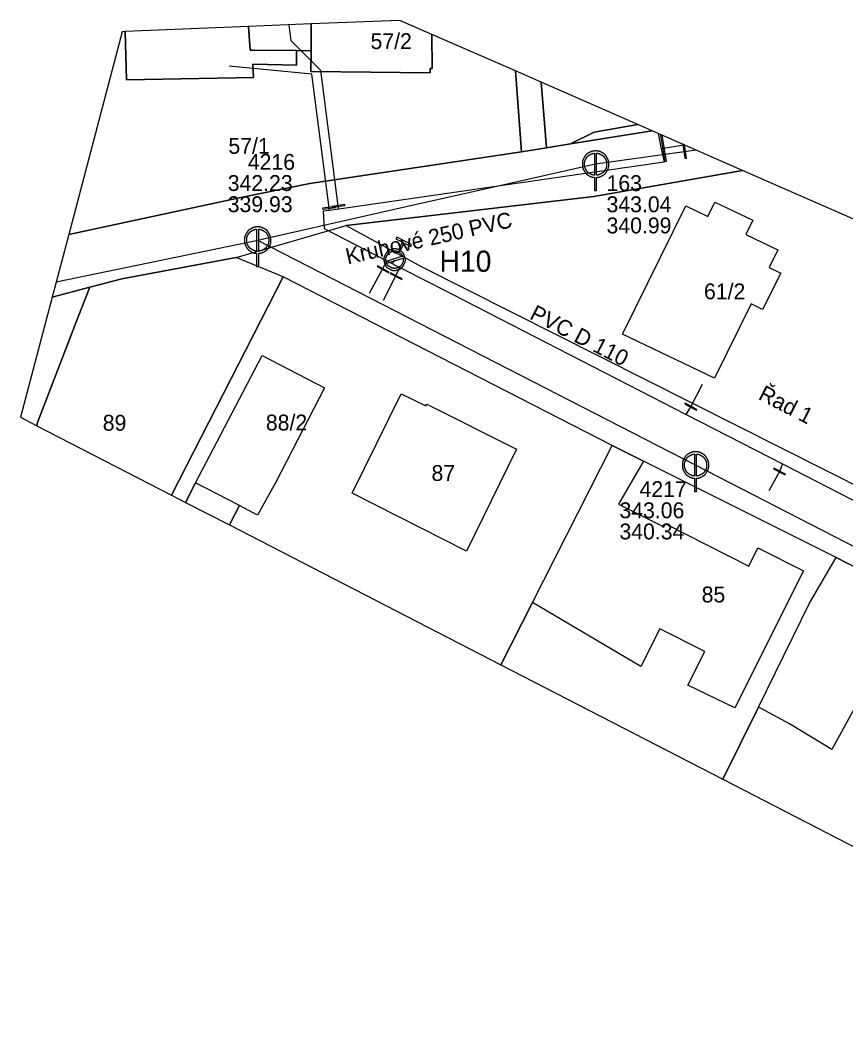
# Model space of a CAD drawing. Extents: x -559654 to -559448, y -1076607 to -1076478.
# Drawn here: x -559654.1 to -559576.1, y -1076574.1 to -1076478 of the extents above; entities that cross this region are included whole.
import ezdxf

# ---------------------------------------------------------------- set-up
doc = ezdxf.new("R2010")
doc.units = 0
for name, color, linetype in [('Armatura vodovodní', 7, 'Continuous'), ('Default', 7, 'Continuous'), ('Hydrant', 7, 'Continuous'), ('Kanalizační stoka', 7, 'Continuous'), ('Kanalizační šachta', 7, 'Continuous'), ('Označení hydrantu', 7, 'Continuous'), ('Parcela-polygon', 7, 'Continuous'), ('Parcela-text', 7, 'Continuous'), ('Popis kmenové stoky', 7, 'Continuous'), ('Popis šachty', 7, 'Continuous'), ('Vodovodní přípojka', 7, 'Continuous'), ('Vodovodní řad', 7, 'Continuous'), ('Řad vodovodní označení', 7, 'Continuous'), ('Řad vodovodní popis', 7, 'Continuous')]:
    doc.layers.add(name, color=color, linetype=linetype)

msp = doc.modelspace()

# ---------------------------------------------------------------- linework, layer by layer
at = {"layer": 'Armatura vodovodní'}
for p, q in [((-559593.444, -1076488.847), (-559593.464, -1076488.838)), ((-559591.347, -1076489.765), (-559591.516, -1076489.691))]:
    msp.add_line(p, q, dxfattribs=at)
for points in [[(-559593.464, -1076488.838), (-559593.6, -1076488.859), (-559593.209, -1076491.329), (-559593.055, -1076491.304), (-559593.444, -1076488.847)], [(-559591.516, -1076489.691), (-559591.306, -1076491.024), (-559591.152, -1076490.999), (-559591.347, -1076489.765)]]:
    msp.add_lwpolyline(points, dxfattribs=at)
for points in [[(-559624.684, -1076495.642), (-559623.444, -1076495.482), (-559623.454, -1076495.405), (-559624.694, -1076495.564)], [(-559625.547, -1076495.824), (-559624.307, -1076495.665), (-559624.317, -1076495.587), (-559625.557, -1076495.747)], [(-559619.308, -1076501.848), (-559619.271, -1076501.779), (-559620.371, -1076501.186), (-559620.408, -1076501.255)], [(-559618.067, -1076502.479), (-559618.032, -1076502.41), (-559619.143, -1076501.839), (-559619.179, -1076501.908)], [(-559590.198, -1076514.822), (-559590.163, -1076514.753), (-559591.274, -1076514.182), (-559591.31, -1076514.251)], [(-559581.82, -1076520.94), (-559581.785, -1076520.871), (-559582.901, -1076520.307), (-559582.936, -1076520.377)]]:
    msp.add_lwpolyline(points, close=True, dxfattribs=at)
at = {"layer": 'Default'}
for points in [[(-559600.365, -1076490.491), (-559600.564, -1076490.599), (-559600.719, -1076490.752), (-559600.832, -1076490.953)], [(-559599.75, -1076490.33), (-559599.962, -1076490.33), (-559600.167, -1076490.384), (-559600.365, -1076490.491)], [(-559600.265, -1076490.674), (-559600.122, -1076490.598), (-559599.984, -1076490.554), (-559599.853, -1076490.542)], [(-559599.136, -1076490.491), (-559599.335, -1076490.384), (-559599.54, -1076490.33), (-559599.75, -1076490.33)], [(-559599.647, -1076490.542), (-559599.516, -1076490.554), (-559599.379, -1076490.598), (-559599.237, -1076490.674)], [(-559598.668, -1076490.953), (-559598.781, -1076490.752), (-559598.937, -1076490.599), (-559599.136, -1076490.491)], [(-559600.832, -1076490.953), (-559600.944, -1076491.153), (-559601, -1076491.362), (-559601, -1076491.58)], [(-559601, -1076491.58), (-559601, -1076491.796), (-559600.945, -1076492.004), (-559600.835, -1076492.203)], [(-559600.792, -1076491.58), (-559600.792, -1076491.399), (-559600.746, -1076491.226), (-559600.653, -1076491.059)], [(-559600.656, -1076492.098), (-559600.747, -1076491.933), (-559600.792, -1076491.761), (-559600.792, -1076491.58)], [(-559600.653, -1076491.059), (-559600.561, -1076490.892), (-559600.431, -1076490.764), (-559600.265, -1076490.674)], [(-559599.237, -1076490.674), (-559599.071, -1076490.764), (-559598.941, -1076490.892), (-559598.848, -1076491.059)], [(-559598.848, -1076491.059), (-559598.754, -1076491.226), (-559598.708, -1076491.399), (-559598.708, -1076491.58)], [(-559598.708, -1076491.58), (-559598.708, -1076491.761), (-559598.753, -1076491.933), (-559598.844, -1076492.098)], [(-559598.5, -1076491.58), (-559598.5, -1076491.362), (-559598.556, -1076491.153), (-559598.668, -1076490.953)], [(-559598.665, -1076492.203), (-559598.555, -1076492.004), (-559598.5, -1076491.796), (-559598.5, -1076491.58)], [(-559600.835, -1076492.203), (-559600.725, -1076492.401), (-559600.571, -1076492.555), (-559600.373, -1076492.664)], [(-559600.27, -1076492.481), (-559600.436, -1076492.39), (-559600.565, -1076492.262), (-559600.656, -1076492.098)], [(-559599.853, -1076492.615), (-559599.989, -1076492.605), (-559600.128, -1076492.561), (-559600.27, -1076492.481)], [(-559599.228, -1076492.481), (-559599.371, -1076492.561), (-559599.511, -1076492.605), (-559599.647, -1076492.615)], [(-559598.844, -1076492.098), (-559598.935, -1076492.262), (-559599.063, -1076492.39), (-559599.228, -1076492.481)], [(-559599.127, -1076492.664), (-559598.929, -1076492.555), (-559598.775, -1076492.401), (-559598.665, -1076492.203)], [(-559600.373, -1076492.664), (-559600.198, -1076492.762), (-559600.025, -1076492.816), (-559599.853, -1076492.828)], [(-559599.647, -1076492.828), (-559599.475, -1076492.816), (-559599.302, -1076492.762), (-559599.127, -1076492.664)], [(-559632.772, -1076498.132), (-559632.884, -1076498.332), (-559632.94, -1076498.542), (-559632.94, -1076498.76)], [(-559632.306, -1076497.671), (-559632.504, -1076497.778), (-559632.66, -1076497.932), (-559632.772, -1076498.132)], [(-559632.733, -1076498.76), (-559632.733, -1076498.579), (-559632.686, -1076498.405), (-559632.594, -1076498.238)], [(-559632.594, -1076498.238), (-559632.501, -1076498.072), (-559632.371, -1076497.943), (-559632.205, -1076497.854)], [(-559631.69, -1076497.51), (-559631.902, -1076497.51), (-559632.107, -1076497.563), (-559632.306, -1076497.671)], [(-559632.205, -1076497.854), (-559632.062, -1076497.777), (-559631.925, -1076497.734), (-559631.793, -1076497.722)], [(-559631.076, -1076497.671), (-559631.276, -1076497.563), (-559631.48, -1076497.51), (-559631.69, -1076497.51)], [(-559631.588, -1076497.722), (-559631.456, -1076497.734), (-559631.319, -1076497.777), (-559631.178, -1076497.854)], [(-559631.178, -1076497.854), (-559631.012, -1076497.943), (-559630.882, -1076498.072), (-559630.788, -1076498.238)], [(-559630.609, -1076498.132), (-559630.721, -1076497.932), (-559630.877, -1076497.778), (-559631.076, -1076497.671)], [(-559630.788, -1076498.238), (-559630.695, -1076498.405), (-559630.648, -1076498.579), (-559630.648, -1076498.76)], [(-559630.44, -1076498.76), (-559630.44, -1076498.542), (-559630.496, -1076498.332), (-559630.609, -1076498.132)], [(-559632.94, -1076498.76), (-559632.94, -1076498.976), (-559632.885, -1076499.184), (-559632.776, -1076499.382)], [(-559632.596, -1076499.277), (-559632.687, -1076499.113), (-559632.733, -1076498.94), (-559632.733, -1076498.76)], [(-559632.21, -1076499.661), (-559632.376, -1076499.569), (-559632.505, -1076499.442), (-559632.596, -1076499.277)], [(-559630.785, -1076499.277), (-559630.876, -1076499.442), (-559631.003, -1076499.569), (-559631.168, -1076499.661)], [(-559630.648, -1076498.76), (-559630.648, -1076498.94), (-559630.693, -1076499.113), (-559630.785, -1076499.277)], [(-559630.605, -1076499.382), (-559630.495, -1076499.184), (-559630.44, -1076498.976), (-559630.44, -1076498.76)], [(-559632.776, -1076499.382), (-559632.666, -1076499.581), (-559632.511, -1076499.735), (-559632.313, -1076499.844)], [(-559632.313, -1076499.844), (-559632.139, -1076499.941), (-559631.965, -1076499.996), (-559631.793, -1076500.007)], [(-559631.793, -1076499.795), (-559631.93, -1076499.785), (-559632.069, -1076499.74), (-559632.21, -1076499.661)], [(-559631.168, -1076499.661), (-559631.311, -1076499.74), (-559631.451, -1076499.785), (-559631.588, -1076499.795)], [(-559631.588, -1076500.007), (-559631.415, -1076499.996), (-559631.242, -1076499.941), (-559631.068, -1076499.844)], [(-559631.068, -1076499.844), (-559630.869, -1076499.735), (-559630.715, -1076499.581), (-559630.605, -1076499.382)], [(-559619.642, -1076500.149), (-559619.768, -1076500.395), (-559619.789, -1076500.649), (-559619.704, -1076500.911)], [(-559619.059, -1076499.652), (-559619.321, -1076499.737), (-559619.515, -1076499.903), (-559619.642, -1076500.149)], [(-559619.551, -1076500.763), (-559619.589, -1076500.581), (-559619.564, -1076500.403), (-559619.475, -1076500.231)], [(-559619.475, -1076500.231), (-559619.372, -1076500.03), (-559619.214, -1076499.896), (-559619.001, -1076499.828)], [(-559618.38, -1076499.676), (-559618.6, -1076499.583), (-559618.827, -1076499.575), (-559619.059, -1076499.652)], [(-559619.001, -1076499.828), (-559618.788, -1076499.759), (-559618.582, -1076499.777), (-559618.381, -1076499.879)], [(-559618.381, -1076499.879), (-559618.209, -1076499.968), (-559618.085, -1076500.098), (-559618.01, -1076500.268)], [(-559617.798, -1076500.3), (-559617.872, -1076500.067), (-559618.01, -1076499.888), (-559618.213, -1076499.762)], [(-559619.704, -1076500.911), (-559619.62, -1076501.174), (-559619.455, -1076501.368), (-559619.211, -1076501.493)], [(-559619.124, -1076501.325), (-559619.296, -1076501.237), (-559619.419, -1076501.109), (-559619.494, -1076500.942)], [(-559618.03, -1076500.974), (-559618.133, -1076501.174), (-559618.291, -1076501.308), (-559618.505, -1076501.376)], [(-559618.447, -1076501.558), (-559618.184, -1076501.474), (-559617.99, -1076501.309), (-559617.863, -1076501.064)], [(-559617.953, -1076500.447), (-559617.916, -1076500.627), (-559617.942, -1076500.802), (-559618.03, -1076500.974)], [(-559617.863, -1076501.064), (-559617.737, -1076500.817), (-559617.715, -1076500.562), (-559617.798, -1076500.3)], [(-559619.211, -1076501.493), (-559618.964, -1076501.62), (-559618.709, -1076501.642), (-559618.447, -1076501.558)], [(-559618.505, -1076501.376), (-559618.719, -1076501.444), (-559618.925, -1076501.427), (-559619.124, -1076501.325)], [(-559591.38, -1076519.39), (-559591.492, -1076519.59), (-559591.548, -1076519.799), (-559591.548, -1076520.017)], [(-559590.913, -1076518.928), (-559591.112, -1076519.036), (-559591.267, -1076519.189), (-559591.38, -1076519.39)], [(-559591.34, -1076520.017), (-559591.34, -1076519.836), (-559591.294, -1076519.663), (-559591.201, -1076519.496)], [(-559591.201, -1076519.496), (-559591.109, -1076519.329), (-559590.979, -1076519.201), (-559590.813, -1076519.111)], [(-559590.298, -1076518.767), (-559590.51, -1076518.767), (-559590.715, -1076518.821), (-559590.913, -1076518.928)], [(-559590.813, -1076519.111), (-559590.67, -1076519.035), (-559590.532, -1076518.991), (-559590.401, -1076518.979)], [(-559589.684, -1076518.928), (-559589.883, -1076518.821), (-559590.088, -1076518.767), (-559590.298, -1076518.767)], [(-559590.195, -1076518.979), (-559590.064, -1076518.991), (-559589.927, -1076519.035), (-559589.785, -1076519.111)], [(-559589.785, -1076519.111), (-559589.619, -1076519.201), (-559589.489, -1076519.329), (-559589.396, -1076519.496)], [(-559589.216, -1076519.39), (-559589.329, -1076519.189), (-559589.485, -1076519.036), (-559589.684, -1076518.928)], [(-559589.396, -1076519.496), (-559589.302, -1076519.663), (-559589.256, -1076519.836), (-559589.256, -1076520.017)], [(-559589.048, -1076520.017), (-559589.048, -1076519.799), (-559589.104, -1076519.59), (-559589.216, -1076519.39)], [(-559591.548, -1076520.017), (-559591.548, -1076520.233), (-559591.493, -1076520.441), (-559591.383, -1076520.64)], [(-559591.204, -1076520.535), (-559591.295, -1076520.37), (-559591.34, -1076520.198), (-559591.34, -1076520.017)], [(-559589.256, -1076520.017), (-559589.256, -1076520.198), (-559589.301, -1076520.37), (-559589.392, -1076520.535)], [(-559589.213, -1076520.64), (-559589.103, -1076520.441), (-559589.048, -1076520.233), (-559589.048, -1076520.017)], [(-559591.383, -1076520.64), (-559591.273, -1076520.838), (-559591.119, -1076520.992), (-559590.921, -1076521.101)], [(-559590.818, -1076520.918), (-559590.984, -1076520.827), (-559591.113, -1076520.699), (-559591.204, -1076520.535)], [(-559590.921, -1076521.101), (-559590.746, -1076521.199), (-559590.573, -1076521.253), (-559590.401, -1076521.265)], [(-559590.401, -1076521.052), (-559590.537, -1076521.042), (-559590.676, -1076520.998), (-559590.818, -1076520.918)], [(-559589.776, -1076520.918), (-559589.919, -1076520.998), (-559590.059, -1076521.042), (-559590.195, -1076521.052)], [(-559590.195, -1076521.265), (-559590.023, -1076521.253), (-559589.85, -1076521.199), (-559589.675, -1076521.101)], [(-559589.392, -1076520.535), (-559589.483, -1076520.699), (-559589.611, -1076520.827), (-559589.776, -1076520.918)], [(-559589.675, -1076521.101), (-559589.477, -1076520.992), (-559589.323, -1076520.838), (-559589.213, -1076520.64)]]:
    msp.add_open_spline(points, degree=2, dxfattribs=at)
at = {"layer": 'Hydrant'}
for points in [[(-559618.213, -1076499.762), (-559617.84, -1076499.036), (-559617.229, -1076499.35), (-559617.143, -1076499.183), (-559618.533, -1076498.469), (-559618.618, -1076498.636), (-559618.007, -1076498.95), (-559618.38, -1076499.676)], [(-559618.01, -1076500.268), (-559619.551, -1076500.763)], [(-559619.494, -1076500.942), (-559617.953, -1076500.447)]]:
    msp.add_lwpolyline(points, dxfattribs=at)
at = {"layer": 'Kanalizační stoka'}
for points in [[(-559590.249, -1076490.246), (-559599.751, -1076491.578)], [(-559599.751, -1076491.578), (-559611.6, -1076494.252), (-559617.94, -1076495.683), (-559631.679, -1076498.783)], [(-559631.679, -1076498.783), (-559650.75, -1076502.72)], [(-559590.298, -1076520.017), (-559631.679, -1076498.783)], [(-559542.148, -1076544.787), (-559590.298, -1076520.017)]]:
    msp.add_lwpolyline(points, dxfattribs=at)
at = {"layer": 'Kanalizační šachta'}
for points in [[(-559599.853, -1076490.542), (-559599.853, -1076492.615)], [(-559599.647, -1076492.615), (-559599.647, -1076490.542)], [(-559599.853, -1076494.08), (-559599.647, -1076494.08), (-559599.647, -1076492.828)], [(-559599.853, -1076492.828), (-559599.853, -1076494.08)], [(-559631.793, -1076497.722), (-559631.793, -1076499.795)], [(-559631.588, -1076499.795), (-559631.588, -1076497.722)], [(-559631.793, -1076501.26), (-559631.588, -1076501.26), (-559631.588, -1076500.007)], [(-559631.793, -1076500.007), (-559631.793, -1076501.26)], [(-559590.401, -1076518.979), (-559590.401, -1076521.052)], [(-559590.195, -1076521.052), (-559590.195, -1076518.979)], [(-559590.401, -1076522.517), (-559590.195, -1076522.517), (-559590.195, -1076521.265)], [(-559590.401, -1076521.265), (-559590.401, -1076522.517)]]:
    msp.add_lwpolyline(points, dxfattribs=at)
at = {"layer": 'Parcela-polygon'}
for p, q in [((-559632.55, -1076478.567), (-559644.223, -1076479.044)), ((-559626.629, -1076478.326), (-559632.55, -1076478.567)), ((-559607.331, -1076482.764), (-559615.215, -1076479.31)), ((-559604.902, -1076483.828), (-559607.331, -1076482.764)), ((-559595.756, -1076487.834), (-559604.902, -1076483.828)), ((-559594.403, -1076488.426), (-559595.756, -1076487.834)), ((-559585.87, -1076492.164), (-559594.403, -1076488.426)), ((-559562.902, -1076502.225), (-559585.87, -1076492.164)), ((-559649.556, -1076498.21), (-559651.127, -1076504.146)), ((-559652.566, -1076516.299), (-559639.844, -1076522.856)), ((-559639.844, -1076522.856), (-559638.51, -1076523.543)), ((-559638.51, -1076523.543), (-559634.361, -1076525.682)), ((-559634.361, -1076525.682), (-559608.706, -1076538.904)), ((-559608.706, -1076538.904), (-559587.727, -1076549.716)), ((-559587.727, -1076549.716), (-559569.856, -1076558.926))]:
    msp.add_line(p, q, dxfattribs=at)
for points in [[(-559615.215, -1076479.31), (-559618.245, -1076477.983), (-559626.629, -1076478.326)], [(-559644.223, -1076479.044), (-559644.488, -1076479.055), (-559649.556, -1076498.21)], [(-559644.223, -1076479.044), (-559644.1, -1076483.61), (-559632.1, -1076483.37), (-559632.14, -1076482.13), (-559628.02, -1076482.21), (-559628.03, -1076480.84), (-559632.19, -1076480.79), (-559632.39, -1076480.79), (-559632.55, -1076478.567)], [(-559615.215, -1076479.31), (-559615.2, -1076482.53), (-559615.4, -1076482.53), (-559615.4, -1076482.93), (-559626.68, -1076482.81), (-559626.64, -1076480.85), (-559628.03, -1076480.84), (-559628.02, -1076482.21), (-559632.14, -1076482.13), (-559632.1, -1076483.37), (-559644.1, -1076483.61), (-559644.223, -1076479.044)], [(-559632.55, -1076478.567), (-559632.39, -1076480.79), (-559632.19, -1076480.79), (-559628.03, -1076480.84), (-559626.64, -1076480.85), (-559626.629, -1076478.326)], [(-559626.629, -1076478.326), (-559626.64, -1076480.85), (-559626.68, -1076482.81), (-559615.4, -1076482.93), (-559615.4, -1076482.53), (-559615.2, -1076482.53), (-559615.215, -1076479.31)], [(-559649.556, -1076498.21), (-559633.28, -1076494.72), (-559626.76, -1076493.41), (-559606.75, -1076490.41), (-559607.331, -1076482.764)], [(-559607.331, -1076482.764), (-559606.75, -1076490.41), (-559604.4, -1076490.03), (-559604.902, -1076483.828)], [(-559604.902, -1076483.828), (-559604.4, -1076490.03), (-559602.13, -1076489.67), (-559599.89, -1076488.55), (-559595.756, -1076487.834)], [(-559594.403, -1076488.426), (-559602.13, -1076489.67), (-559604.4, -1076490.03), (-559606.75, -1076490.41), (-559626.76, -1076493.41), (-559633.28, -1076494.72), (-559649.556, -1076498.21)], [(-559595.756, -1076487.834), (-559599.89, -1076488.55), (-559602.13, -1076489.67), (-559594.403, -1076488.426)], [(-559651.127, -1076504.146), (-559647.56, -1076503.2), (-559644.55, -1076502.4), (-559633.72, -1076500.39), (-559623.33, -1076497.36), (-559599.9, -1076494.63), (-559585.87, -1076492.164)], [(-559585.87, -1076492.164), (-559599.9, -1076494.63), (-559623.33, -1076497.36), (-559616.19, -1076501.28), (-559573.81, -1076522.62), (-559565.46, -1076506.3), (-559562.902, -1076502.225)], [(-559588.51, -1076511.82), (-559597.22, -1076507.66), (-559591.23, -1076495.51), (-559589.14, -1076496.51), (-559588.49, -1076495.16), (-559584.88, -1076496.88), (-559585.53, -1076498.23), (-559582.52, -1076499.67), (-559583.34, -1076501.33), (-559582.25, -1076501.87), (-559583.98, -1076505.31), (-559585.04, -1076504.78), (-559588.51, -1076511.82)], [(-559639.844, -1076522.856), (-559629.27, -1076502.23), (-559633.72, -1076500.39), (-559644.55, -1076502.4), (-559647.56, -1076503.2), (-559648.65, -1076506.01), (-559652.51, -1076515.99), (-559652.566, -1076516.299)], [(-559608.706, -1076538.904), (-559605.71, -1076533), (-559598.18, -1076518.16), (-559629.27, -1076502.23), (-559639.844, -1076522.856)], [(-559652.566, -1076516.299), (-559652.51, -1076515.99), (-559648.65, -1076506.01), (-559647.56, -1076503.2), (-559651.127, -1076504.146)], [(-559651.127, -1076504.146), (-559654.129, -1076515.494), (-559652.566, -1076516.299)], [(-559638.51, -1076523.543), (-559637.58, -1076521.71), (-559635.9, -1076518.51), (-559631.27, -1076509.65), (-559625.37, -1076512.71), (-559629.99, -1076521.64), (-559631.71, -1076524.76), (-559633.42, -1076523.85), (-559634.361, -1076525.682)], [(-559615.79, -1076514.42), (-559615.71, -1076514.27), (-559607.23, -1076518.52), (-559611.96, -1076528.15), (-559622.75, -1076522.67), (-559618.13, -1076513.29), (-559615.79, -1076514.42)], [(-559587.727, -1076549.716), (-559584.34, -1076542.9), (-559579.53, -1076533.07), (-559577, -1076528.76), (-559595.22, -1076519.64), (-559597.57, -1076523.72), (-559593.3, -1076525.87), (-559593.14, -1076525.56), (-559585.27, -1076529.56), (-559584.4, -1076527.85), (-559580.11, -1076530), (-559586.58, -1076542.95), (-559591.03, -1076540.81), (-559589.41, -1076537.64), (-559593.68, -1076535.49), (-559595.48, -1076539.07), (-559605.71, -1076533), (-559608.706, -1076538.904)], [(-559634.361, -1076525.682), (-559633.42, -1076523.85), (-559637.58, -1076521.71), (-559638.51, -1076523.543)], [(-559569.856, -1076558.926), (-559559.21, -1076537.91), (-559568.79, -1076532.99), (-559570.76, -1076536.75), (-559564.14, -1076540.06), (-559567.52, -1076546.81), (-559575.28, -1076543.01), (-559577.42, -1076546.89), (-559581.41, -1076544.47), (-559584.1, -1076543.03), (-559584.34, -1076542.9), (-559587.727, -1076549.716)]]:
    msp.add_lwpolyline(points, dxfattribs=at)
for points in [[(-559582.25, -1076501.87), (-559583.98, -1076505.31), (-559585.04, -1076504.78), (-559588.51, -1076511.82), (-559597.22, -1076507.66), (-559591.23, -1076495.51), (-559589.14, -1076496.51), (-559588.49, -1076495.16), (-559584.88, -1076496.88), (-559585.53, -1076498.23), (-559582.52, -1076499.67), (-559583.34, -1076501.33)], [(-559598.18, -1076518.16), (-559629.27, -1076502.23), (-559633.72, -1076500.39), (-559623.33, -1076497.36), (-559616.19, -1076501.28), (-559573.81, -1076522.62), (-559555.89, -1076531.62), (-559538.18, -1076540.8), (-559520.56, -1076549.81), (-559502.55, -1076559.13), (-559485.32, -1076568.19), (-559489.07, -1076574.14), (-559505.11, -1076565.7), (-559518.69, -1076558.79), (-559538.34, -1076548.73), (-559546.54, -1076544.48), (-559559.21, -1076537.91), (-559568.79, -1076532.99), (-559577, -1076528.76), (-559595.22, -1076519.64)], [(-559637.58, -1076521.71), (-559635.9, -1076518.51), (-559631.27, -1076509.65), (-559625.37, -1076512.71), (-559629.99, -1076521.64), (-559631.71, -1076524.76), (-559633.42, -1076523.85)], [(-559607.23, -1076518.52), (-559611.96, -1076528.15), (-559622.75, -1076522.67), (-559618.13, -1076513.29), (-559615.79, -1076514.42), (-559615.71, -1076514.27)], [(-559593.68, -1076535.49), (-559595.48, -1076539.07), (-559605.71, -1076533), (-559598.18, -1076518.16), (-559595.22, -1076519.64), (-559597.57, -1076523.72), (-559593.3, -1076525.87), (-559593.14, -1076525.56), (-559585.27, -1076529.56), (-559584.4, -1076527.85), (-559580.11, -1076530), (-559586.58, -1076542.95), (-559591.03, -1076540.81), (-559589.41, -1076537.64)], [(-559568.79, -1076532.99), (-559570.76, -1076536.75), (-559564.14, -1076540.06), (-559567.52, -1076546.81), (-559575.28, -1076543.01), (-559577.42, -1076546.89), (-559581.41, -1076544.47), (-559584.1, -1076543.03), (-559584.34, -1076542.9), (-559579.53, -1076533.07), (-559577, -1076528.76)]]:
    msp.add_lwpolyline(points, close=True, dxfattribs=at)
at = {"layer": 'Vodovodní přípojka'}
for points in [[(-559624.029, -1076495.839), (-559624.069, -1076495.524), (-559625.716, -1076482.727), (-559628.528, -1076479.914), (-559628.703, -1076478.41)], [(-559624.9, -1076495.951), (-559624.931, -1076495.709), (-559624.932, -1076495.707), (-559626.559, -1076483.055), (-559634.387, -1076482.305)], [(-559619.475, -1076500.701), (-559621.147, -1076503.805)], [(-559618.245, -1076501.333), (-559619.829, -1076504.47)], [(-559591.192, -1076515.237), (-559590.737, -1076514.503), (-559589.639, -1076512.374)], [(-559582.087, -1076519.916), (-559582.361, -1076520.624), (-559583.375, -1076522.465)]]:
    msp.add_lwpolyline(points, dxfattribs=at)
at = {"layer": 'Vodovodní řad'}
for points in [[(-559593.843, -1076488.672), (-559593.538, -1076490.114), (-559593.267, -1076491.395)], [(-559591.348, -1076489.765), (-559591.424, -1076489.777), (-559591.966, -1076489.87), (-559593.327, -1076490.082), (-559593.538, -1076490.114)], [(-559593.267, -1076491.395), (-559624.029, -1076495.839), (-559624.9, -1076495.951), (-559625.488, -1076496.027), (-559625.404, -1076497.654), (-559619.475, -1076500.701), (-559618.245, -1076501.333), (-559615.438, -1076502.776), (-559591.192, -1076515.237), (-559582.087, -1076519.916), (-559544.618, -1076539.173), (-559534.23, -1076544.512), (-559532.371, -1076545.439), (-559530.757, -1076546.244), (-559525.83, -1076548.702), (-559513.543, -1076555.186), (-559509.507, -1076557.365), (-559508.97, -1076557.619), (-559494.604, -1076565.581), (-559494.539, -1076565.616), (-559485.627, -1076570.145)], [(-559618.93, -1076500.981), (-559618.752, -1076500.605)]]:
    msp.add_lwpolyline(points, dxfattribs=at)

# ---------------------------------------------------------------- texts
at = {"layer": 'Označení hydrantu'}
msp.add_text('H10', height=2, dxfattribs=at).set_placement((-559614.502, -1076501.751))
at = {"layer": 'Parcela-text'}
for s, p in [('57/2', (-559621.02, -1076480.7)), ('57/1', (-559634.46, -1076490.6)), ('61/2', (-559589.5, -1076504.35)), ('89', (-559646.34, -1076516.77)), ('88/2', (-559630.92, -1076516.75)), ('87', (-559615.26, -1076521.52)), ('85', (-559589.72, -1076533))]:
    msp.add_text(s, height=1.5, dxfattribs=at).set_placement(p)
at = {"layer": 'Popis kmenové stoky'}
msp.add_text('Kruhové 250 PVC', height=1.5, rotation=12.71909, dxfattribs=at).set_placement((-559623.185, -1076501.052))
at = {"layer": 'Popis šachty'}
for s, p in [('4216', (-559632.624, -1076492.112)), ('342.23', (-559634.523, -1076494.112)), ('163', (-559598.713, -1076494.119)), ('339.93', (-559634.523, -1076496.112)), ('343.04', (-559598.713, -1076496.119)), ('340.99', (-559598.713, -1076498.119)), ('4217', (-559595.594, -1076523.044)), ('343.06', (-559597.493, -1076525.044)), ('340.34', (-559597.493, -1076527.044))]:
    msp.add_text(s, height=1.5, dxfattribs=at).set_placement(p)
at = {"layer": 'Řad vodovodní označení'}
msp.add_text('Řad 1', height=1.5, rotation=332.79956, dxfattribs=at).set_placement((-559584.463, -1076513.748))
at = {"layer": 'Řad vodovodní popis'}
msp.add_text('PVC D 110', height=1.5, rotation=332.79956, dxfattribs=at).set_placement((-559606.073, -1076506.146))

doc.saveas('drawing.dxf')
